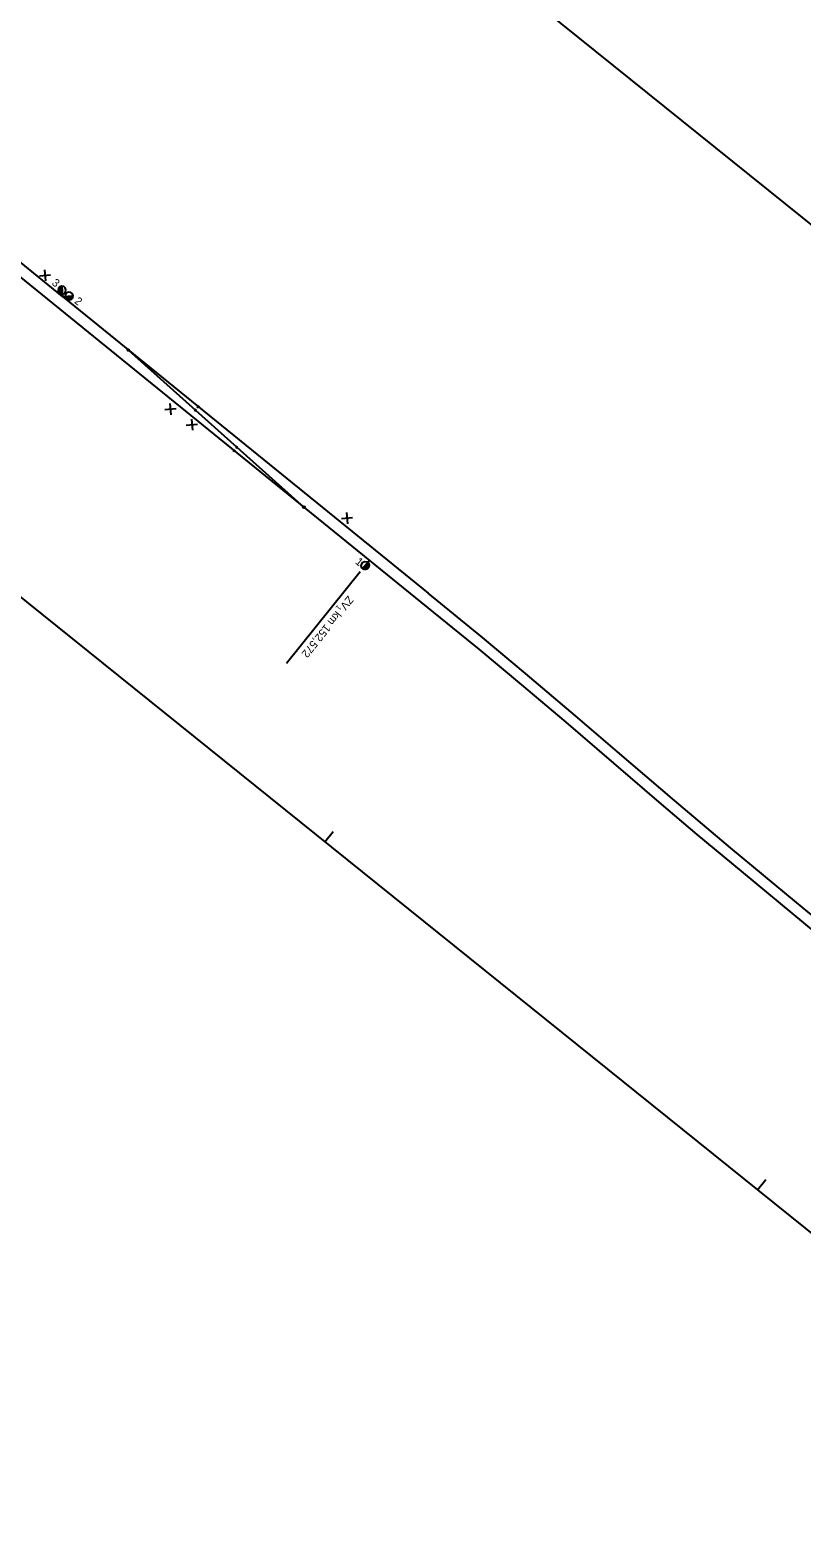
# Model space of a CAD drawing. Extents: x -491586 to -489736, y -1309039 to -1307479.
# Drawn here: x -490388 to -490096, y -1309026 to -1308456 of the extents above; entities that cross this region are included whole.
import ezdxf

# ---------------------------------------------------------------- set-up
doc = ezdxf.new("R2010")
doc.units = 0
for name, color, linetype in [('Level 1', 7, 'Continuous'), ('Level 11', 7, 'Continuous'), ('Level 61', 7, 'Continuous')]:
    doc.layers.add(name, color=color, linetype=linetype)

msp = doc.modelspace()

# ---------------------------------------------------------------- linework, layer by layer
at = {"layer": 'Level 1'}
for p, q in [((-490420.1, -1308526.96), (-490240.37, -1308672.68)), ((-490375.84, -1308557.18), (-490408.13, -1308530.96)), ((-490375.84, -1308557.18), (-490237.65, -1308669.34)), ((-490350.97, -1308577.36), (-490350.97, -1308577.36)), ((-490350.97, -1308577.36), (-490284.67, -1308636.77)), ((-490325.98, -1308600.42), (-490325.34, -1308599.65)), ((-490325.66, -1308600.04), (-490325.66, -1308600.04)), ((-490324.9, -1308599.17), (-490324.26, -1308598.4)), ((-490324.58, -1308598.79), (-490324.58, -1308598.79)), ((-490311.37, -1308615.73), (-490310.73, -1308614.96)), ((-490311.05, -1308615.35), (-490311.05, -1308615.35)), ((-490310.31, -1308614.47), (-490309.67, -1308613.7)), ((-490309.99, -1308614.08), (-490309.99, -1308614.08)), ((-490284.67, -1308636.77), (-490284.67, -1308636.77)), ((-490240.37, -1308672.68), (-490218.48, -1308690.44)), ((-490217.04, -1308686.03), (-490237.65, -1308669.34)), ((-490218.48, -1308690.44), (-490202.26, -1308704)), ((-490200.83, -1308699.69), (-490217.04, -1308686.03)), ((-490181.84, -1308715.63), (-490200.83, -1308699.69)), ((-490202.26, -1308704), (-490185.59, -1308718.1)), ((-490185.59, -1308718.1), (-490149.52, -1308749.07)), ((-490165.98, -1308729.25), (-490181.84, -1308715.63)), ((-490144.51, -1308747.74), (-490165.98, -1308729.25)), ((-490123.23, -1308765.56), (-490144.51, -1308747.74)), ((-490149.52, -1308749.07), (-490135.96, -1308760.48)), ((-490135.96, -1308760.48), (-490122.96, -1308771.34)), ((-490098.3, -1308786.21), (-490123.23, -1308765.56)), ((-490122.96, -1308771.34), (-490091.28, -1308797.58)), ((-490058.53, -1308819.1), (-490098.3, -1308786.21))]:
    msp.add_line(p, q, dxfattribs=at)
for points in [[(-490350.73, -1308577.04), (-490350.58, -1308577.41), (-490350.81, -1308577.72), (-490351.21, -1308577.68), (-490351.37, -1308577.31), (-490351.13, -1308576.99), (-490350.73, -1308577.04)], [(-490284.43, -1308636.45), (-490284.27, -1308636.81), (-490284.51, -1308637.13), (-490284.91, -1308637.09), (-490285.06, -1308636.72), (-490284.82, -1308636.4), (-490284.43, -1308636.45)]]:
    msp.add_lwpolyline(points, dxfattribs=at)
at = {"layer": 'Level 11'}
for p, q in [((-490382.69, -1308547), (-490382.26, -1308551.26)), ((-490384.6, -1308549.35), (-490380.35, -1308548.91)), ((-490375.84, -1308557.18), (-490375.84, -1308557.18)), ((-490337.2, -1308599.9), (-490332.95, -1308599.47)), ((-490335.29, -1308597.56), (-490334.86, -1308601.81)), ((-490329.07, -1308605.81), (-490324.82, -1308605.37)), ((-490327.16, -1308603.46), (-490326.73, -1308607.72)), ((-490268.53, -1308638.77), (-490268.09, -1308643.02)), ((-490270.43, -1308641.11), (-490266.18, -1308640.68)), ((-490259.79, -1308656.94), (-490262.32, -1308659.97)), ((-490259.79, -1308656.94), (-490259.79, -1308656.94)), ((-490263.33, -1308661.28), (-490291.12, -1308695.84))]:
    msp.add_line(p, q, dxfattribs=at)
for points in [[(-490375.92, -1308556.21), (-490375.2, -1308555.94), (-490374.7, -1308555.34), (-490374.56, -1308554.58), (-490374.83, -1308553.85), (-490375.43, -1308553.35), (-490376.19, -1308553.22), (-490376.92, -1308553.49), (-490377.42, -1308554.08), (-490377.55, -1308554.85), (-490377.29, -1308555.57), (-490376.69, -1308556.07), (-490375.92, -1308556.21), (-490376.1, -1308555.85), (-490376.73, -1308555.91), (-490377.04, -1308555.65), (-490376.19, -1308555.58), (-490376.19, -1308555.25), (-490377.2, -1308555.38), (-490377.34, -1308555.08), (-490376.21, -1308554.97), (-490376.24, -1308554.69), (-490377.4, -1308554.76), (-490377.36, -1308554.47), (-490376.23, -1308554.37), (-490376.26, -1308554.09), (-490377.24, -1308554.18), (-490377.03, -1308553.84), (-490376.32, -1308553.78), (-490376.31, -1308553.46), (-490376.67, -1308553.49)], [(-490376.19, -1308553.23), (-490375.84, -1308557.18), (-490371.89, -1308556.82)], [(-490371.88, -1308556.82), (-490372.15, -1308556.09), (-490372.74, -1308555.59), (-490373.55, -1308555.46), (-490374.24, -1308555.73), (-490374.73, -1308556.32), (-490374.87, -1308557.09), (-490374.6, -1308557.82), (-490374, -1308558.31), (-490373.28, -1308558.45), (-490372.51, -1308558.18), (-490372.01, -1308557.58), (-490371.88, -1308556.82), (-490372.19, -1308557.02), (-490372.15, -1308557.52), (-490372.44, -1308557.86), (-490372.51, -1308557.09), (-490372.79, -1308557.11), (-490372.7, -1308558.1), (-490373.01, -1308558.23), (-490373.11, -1308557.11), (-490373.42, -1308557.17), (-490373.29, -1308558.26), (-490373.61, -1308558.25), (-490373.7, -1308557.2), (-490373.99, -1308557.22), (-490373.9, -1308558.21), (-490374.24, -1308557.92), (-490374.31, -1308557.22), (-490374.59, -1308557.24), (-490374.55, -1308557.66)], [(-490262.01, -1308660.23), (-490262.63, -1308659.71), (-490262.89, -1308658.97), (-490262.75, -1308658.23), (-490262.25, -1308657.63), (-490261.53, -1308657.36), (-490260.77, -1308657.49), (-490260.15, -1308658), (-490259.9, -1308658.72), (-490260.02, -1308659.48), (-490260.53, -1308660.09), (-490261.26, -1308660.35), (-490262.01, -1308660.23), (-490261.66, -1308660.19), (-490262.04, -1308659.87), (-490261.85, -1308659.64), (-490261.2, -1308660.19), (-490260.85, -1308660.09), (-490261.66, -1308659.41), (-490261.47, -1308659.18), (-490260.58, -1308659.92), (-490260.39, -1308659.69), (-490261.27, -1308658.95), (-490261.08, -1308658.72), (-490260.2, -1308659.46), (-490260.12, -1308659.13), (-490260.89, -1308658.49), (-490260.7, -1308658.26), (-490260.05, -1308658.81), (-490260.12, -1308658.35), (-490260.51, -1308658.03)]]:
    msp.add_lwpolyline(points, dxfattribs=at)
at = {"layer": 'Level 61'}
for p, q in [((-490908.8, -1307873.79), (-489763.26, -1308795.01)), ((-489949.39, -1309026.46), (-491094.92, -1308105.24)), ((-490276.68, -1308763.25), (-490273.55, -1308759.36)), ((-490113.03, -1308894.85), (-490109.9, -1308890.96))]:
    msp.add_line(p, q, dxfattribs=at)

# ---------------------------------------------------------------- texts
at = {"layer": 'Level 11'}
for s, height, rotation, p in [('3', 3, 321.1944, (-490380.16, -1308552.42)), ('2', 3, 321.1944, (-490371.63, -1308559.34)), ('1', 3, 321.1944, (-490265.41, -1308657.87)), ('ZV  km 152,572', 3, 231.1944, (-490267.9, -1308670.06)), ('1', 2, 231.1944, (-490271.78, -1308673.57))]:
    msp.add_text(s, height=height, rotation=rotation, dxfattribs=at).set_placement(p)

doc.saveas('drawing.dxf')
